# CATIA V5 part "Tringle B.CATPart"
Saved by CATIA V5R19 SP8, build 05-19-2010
Part number: Tringle B
Bounding box of the stored display mesh (mm): x 0 to 200, y -7.5 to 7.5, z -7.312 to 7.312
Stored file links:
  F:\CFAO\Hberriche\Tringle B.CATPart
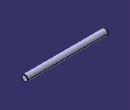
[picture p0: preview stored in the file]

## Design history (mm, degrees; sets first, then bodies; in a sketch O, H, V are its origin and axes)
Body1 (main body)
  Sketch1 on yz-plane, origin (0, 0, 0), H (0, 1, 0), V (0, 0, 1)
    circle A1 centre (0, 0) radius 7.5
    radius A1 = 7.5
  Pad1: profile Sketch1, direction (1, 0, 0), length 200
  Fillet1: radius 1, on edge [face of Pad1 from Sketch1.A1 | end face of Pad1]
  Fillet2: radius 1, on edge [start face of Pad1 | face of Pad1 from Sketch1.A1]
